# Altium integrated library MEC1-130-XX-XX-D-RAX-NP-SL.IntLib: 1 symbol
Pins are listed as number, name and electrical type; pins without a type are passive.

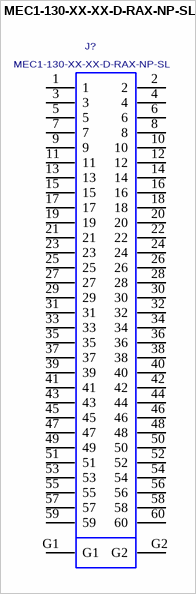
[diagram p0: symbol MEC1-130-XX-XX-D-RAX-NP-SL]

## MEC1-130-XX-XX-D-RAX-NP-SL
designator J?
1MM MEC1-RA ASSEMBLY, 60 PINS.; MANUFACTURER: SAMTEC
footprint MEC1-130-XX-XX-D-RAX-NP-SL
pins: 1, 2, 3, 4, 5, 6, 7, 8, 9, 10, 11, 12, 13, 14, 15, 16, 17, 18, 19, 20, 21, 22, 23, 24, 25, 26, 27, 28, 29, 30, 31, 32, 33, 34, 35, 36, 37, 38, 39, 40, 41, 42, 43, 44, 45, 46, 47, 48, 49, 50, 51, 52, 53, 54, 55, 56, 57, 58, 59, 60, G1, G2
